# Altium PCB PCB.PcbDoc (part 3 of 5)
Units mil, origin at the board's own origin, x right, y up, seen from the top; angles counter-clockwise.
Board outline 6700 x 6500 mil, 2 copper layers (Top Layer, Bottom Layer); 203 components, 278 nets, 1296 pads, 461 vias.
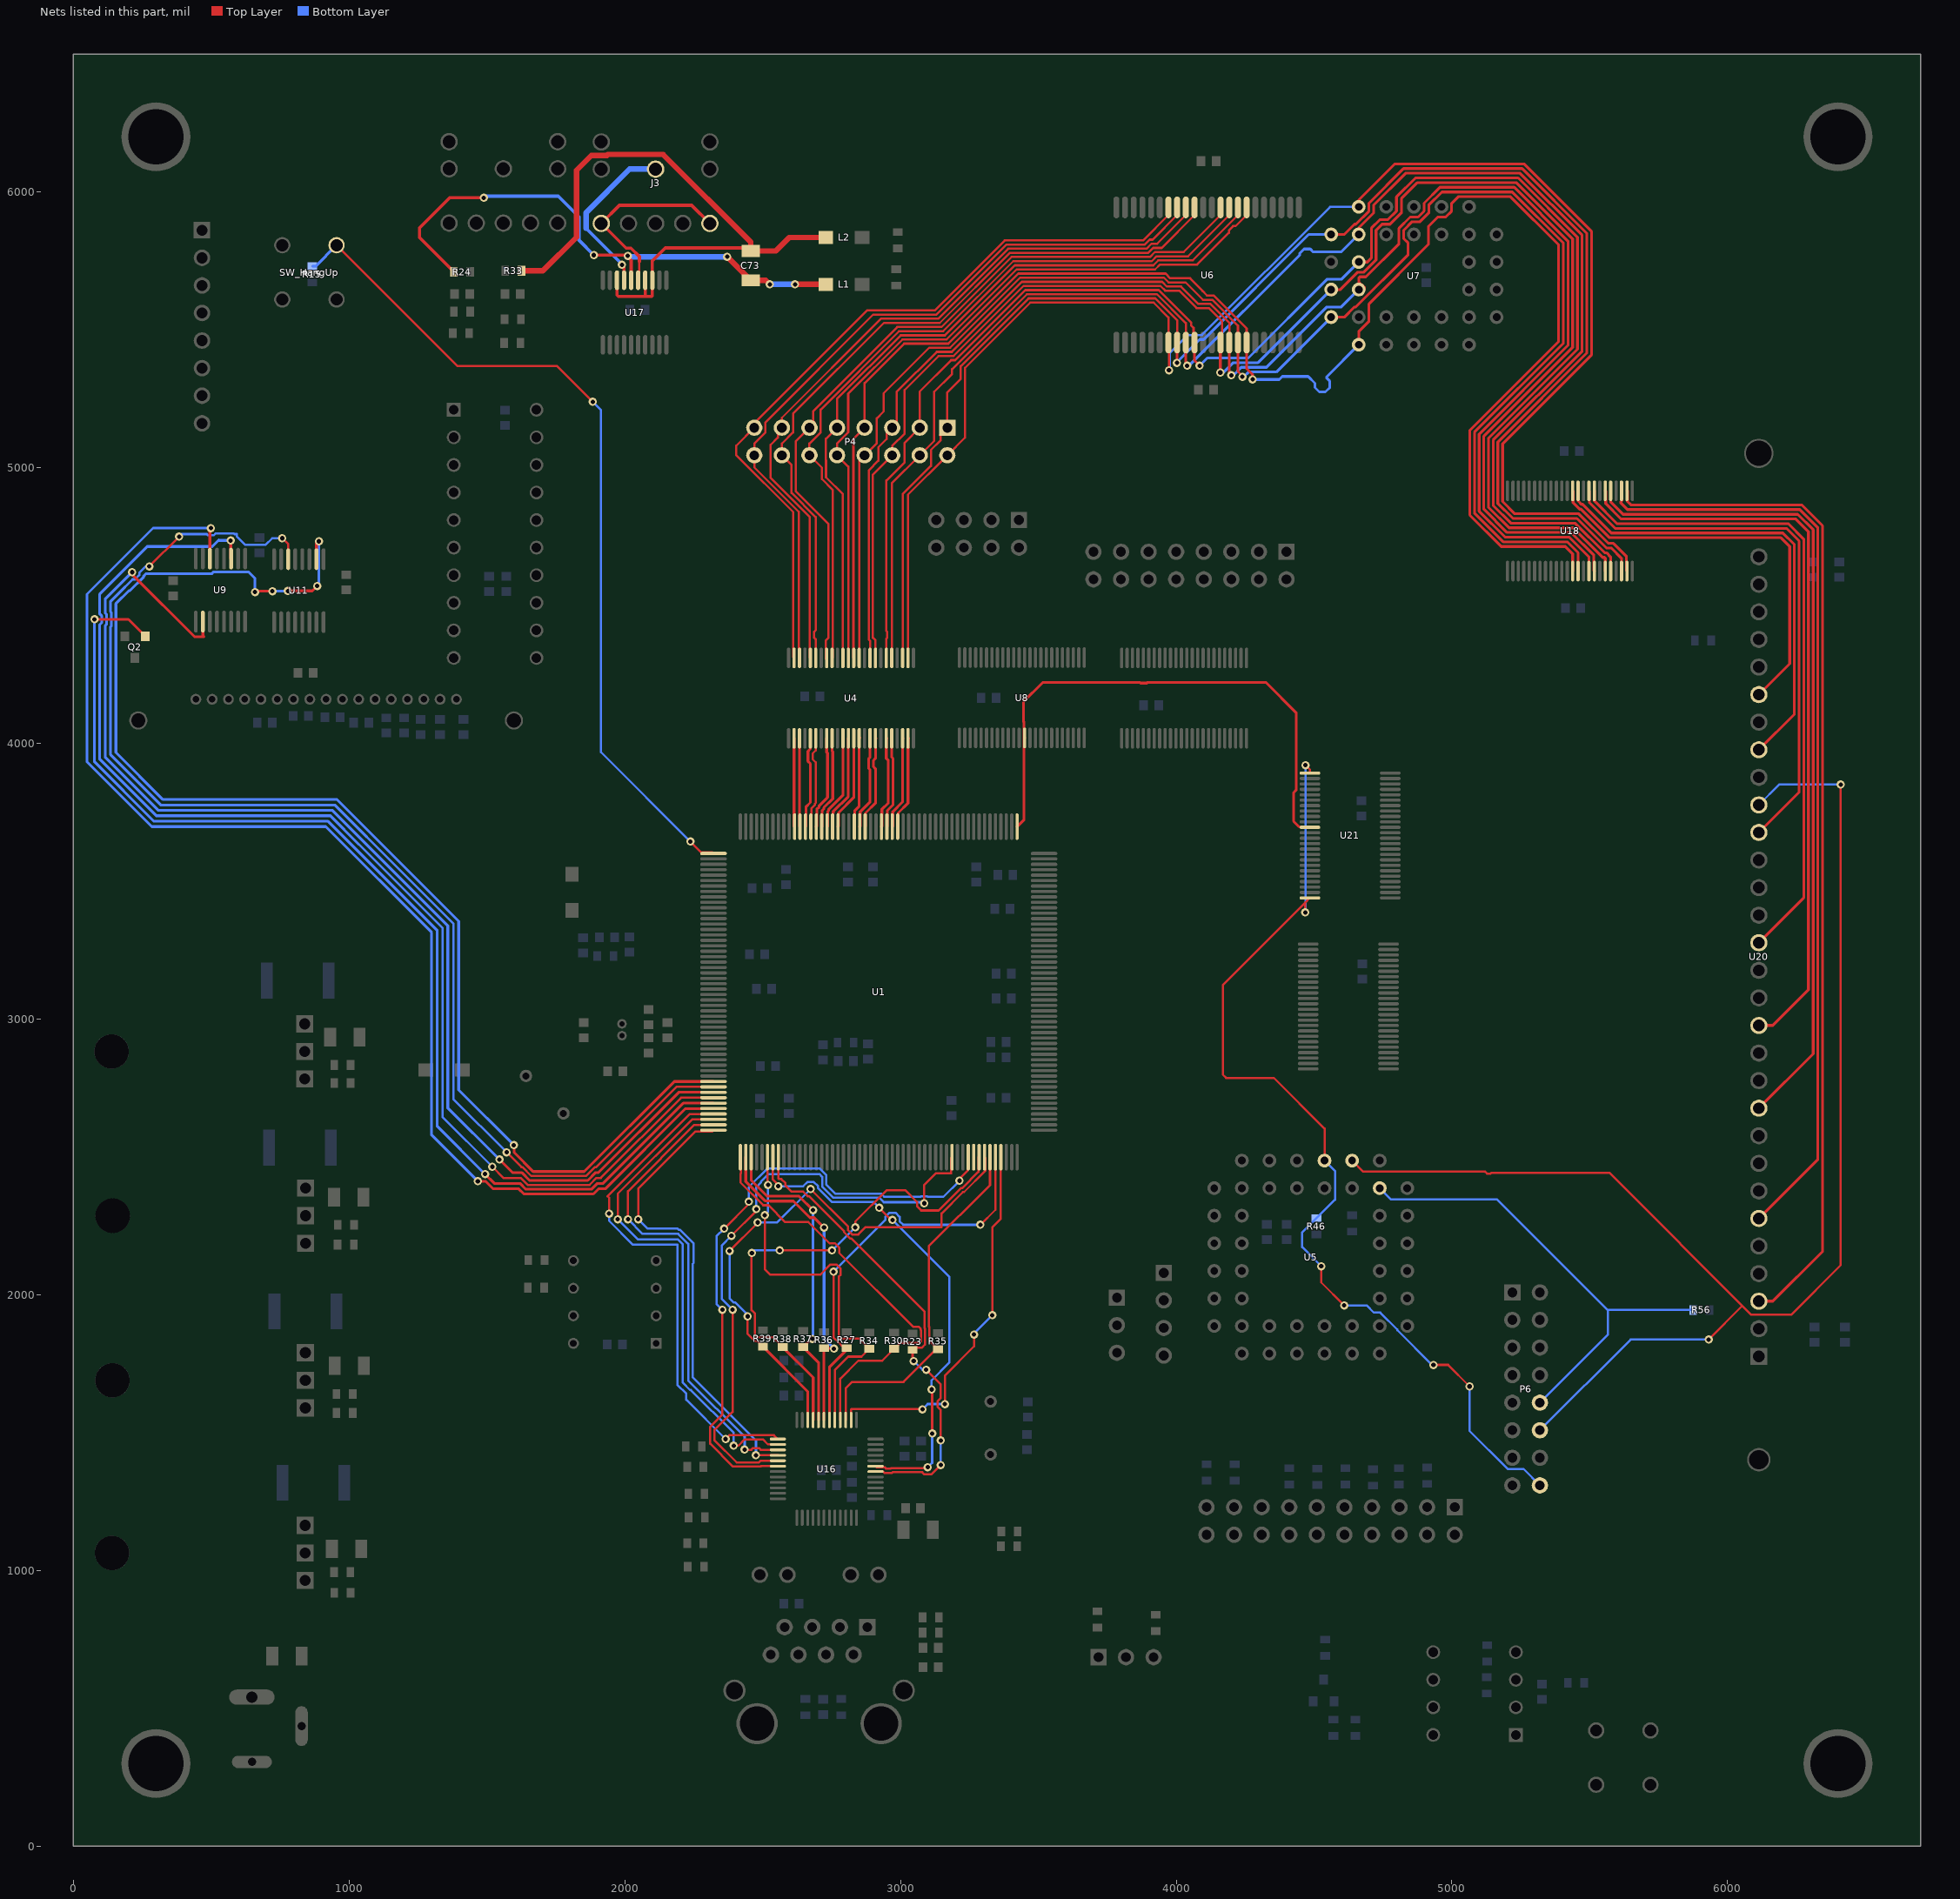
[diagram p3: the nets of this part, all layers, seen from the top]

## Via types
v1: diameter 30, hole 16, Top Layer to Bottom Layer, 461 vias

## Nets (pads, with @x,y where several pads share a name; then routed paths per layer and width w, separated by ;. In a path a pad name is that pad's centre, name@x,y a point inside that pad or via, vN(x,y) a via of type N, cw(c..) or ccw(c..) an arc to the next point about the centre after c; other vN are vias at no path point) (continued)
ADDR19: U1.157 U8.37 U21.35 | length 1997.8
  Top Layer w10: U1.157@3423.15,3698.23 3448.22,3723.3 U8.37@3448.22,4018.22 ; U8.37@3450,4020 U8.37@3448.22,4018.22 ; U21.35@4485,3695.63 4483.22,3697.41 4446.09,3697.41 4425.87,3717.63 4425.87,3821.31 4435,3830.44 4435,4111.81 4325.75,4221.06 3895.25,4221.06 3893.18,4219 3870.82,4219 3868.75,4221.06 3611.69,4221.06 3611.63,4221 3516,4221 3446,4151 3446,4078.77 3448.22,4076.55 U8.37@3448.22,4018.22
AUD_VDD: C73.2 L1.1 R24.2 U17.6 | length 2019.5
  Top Layer w8: U17.6@2023.18,5680 U17.6@2027,5683.82
  Top Layer w12: R24.2@1380.47,5710 1256,5834.47 1256,5870 1365,5979 v1(1489,5979) ; v1(1888,5771) 2004.25,5771 2009.13,5766.13 2023.18,5752.07 U17.6@2023.18,5680
  Top Layer w20: v1@2009.13,5766.13 v1(2011,5768) ; v1(2371.85,5765) C73.2@2457,5679.85 2511.15,5679.85 v1(2526,5665) ; v1(2618,5665) L1.1@2729.06,5665
  Bottom Layer w12: v1(1489,5979) 1495,5985 1759,5985 1834,5910 1834,5825 v1(1888,5771)
  Bottom Layer w20: v1(2011,5768) 2008,5765 v1(2371.85,5765) ; v1(2526,5665) v1(2618,5665)
AUD_VSS: C73.1 L2.1 R33.1 U17.3 U17.4 U17.8 | length 2353.2
  Top Layer w12: U17.8@1972,5680 1972,5626 1977,5621 2071,5621 ; U17.4@2074.36,5680 2074.36,5624.36 2071,5621 ; C73.1@2457,5786.15 2457,5797 2147,5797 2099.95,5749.95 U17.3@2099.95,5680 2099.95,5622.95 2098,5621 2071,5621
  Top Layer w20: R33.1@1625.53,5714 1703,5714 1825,5836 1825,6079 1878.78,6132.78 1935.24,6132.78 1938.46,6136 2139,6136 2457,5818 C73.1@2457,5797 ; C73.1@2457,5786.15 2548.15,5786.15 2597,5835 L2.1@2729.06,5835
BTN_HANGUP: R15.1 SW_HangUp.1 U1.1 | length 3127.1
  Top Layer w8: SW_HangUp.1@955,5806.85 1392.85,5369 1754,5369 v1(1884,5239) ; v1(2238,3644) 2277.21,3604.79 2317.77,3604.79 U1.1@2321.77,3600.79
  Bottom Layer w8: v1(1884,5239) 1914,5209 1914,3968 v1(2238,3644)
  Bottom Layer w10: R15.1@867,5730.53 878.68,5730.53 SW_HangUp.1@955,5806.85
CAS: P6.10 R56.2 U5.19 | length 1758
  Bottom Layer w8: U5.19@4738,2387 4779,2346 5164,2346 5565,1945 ; P6.10@5319,1609 5565,1855 5565,1945 ; R56.2@5875,1945 5565,1945
COL_ADDR_EN: P6.16 R46.1 U5.22 U21.25 U21.48 | length 3672.1
  Top Layer w8: v1(4468,3387) 4468,3422.73 ; v1(4469,3921) 4485,3905 U21.25@4485,3892.48 ; U21.48@4485,3439.73 4468,3422.73 ; v1(4526,2104) 4526,2045 v1(4609,1962) ; U5.22@4538,2487 4538,2603 4354,2787 4181,2787 4169,2799 4169,3123.73 4468,3422.73 ; v1(4933,1746) 4986,1746 v1(5064,1668)
  Bottom Layer w8: v1(4468,3387) 4469,3388 v1(4469,3921) ; v1(4526,2104) 4457,2173 4457,2226.53 R46.1@4509,2278.53 4576,2345.53 4576,2449 U5.22@4538,2487 ; v1(4609,1962) 4690.88,1962 4716.88,1936 4739.91,1936 4802,1873.91 4802,1872.09 4928.09,1746 v1(4933,1746) ; v1(5064,1668) 5064,1506.69 5202.21,1368.47 5259.53,1368.47 P6.16@5319,1309
D_3V3B0: P4.2 U4.2 U6.7 U7.13 U18.47 | length 5884.2
  Top Layer w8: U4.2@3027.48,4310 3027.48,4902.48 P4.2@3170,5045 3234,5109 3234,5361.8 3471.2,5599 3918,5599 3972.02,5544.98 U6.7@3972.02,5454 3974,5452.02 v1(3974,5353.67)
  Top Layer w10: U7.13@4662,5946 4662,5970.45 4793.55,6102 5261.29,6102 5506,5857.29 5506,5408.46 5183.67,5086.13 5183.67,4877.43 5228.16,4832.94 5460.35,4832.94 5567.89,4725.4 5585.52,4725.4 5632.87,4678.05 5632.87,4626.78 U18.47@5634.65,4625
  Bottom Layer w8: v1(3974,5353.67) 3976.67,5351 3976.67,5414.67 4043,5481 4093,5481 4558,5946 U7.13@4662,5946
D_3V3B1: P4.1 U4.3 U6.8 U7.14 U18.46 | length 5807.2
  Top Layer w8: U4.3@3007.8,4310 3007.8,4904.01 3110.53,5006.74 3110.53,5064.31 3145,5098.79 3145,5116.6 3144.47,5117.13 3144.47,5119.47 P4.1@3170,5145 3170,5273 3219,5322 3219,5368.02 3464.98,5614 3924.21,5614 4003.51,5534.7 U6.8@4003.51,5454
  Top Layer w10: v1(4003,5380) 4003,5447.49 4000,5450.49 U6.8@4003.51,5454 ; U7.14@4562,5846 4609.67,5846 4646.67,5883 4651.33,5883 4699,5930.67 4699,5959.37 4824.63,6085 5254.25,6085 5489,5850.25 5489,5415.5 5166.67,5093.17 5166.67,4870.38 5221.12,4815.94 5453.31,4815.94 5560.85,4708.4 5578.48,4708.4 5614.96,4671.92 U18.46@5614.96,4625
  Bottom Layer w10: v1(4003,5380) 4003,5383 4085,5465 4099.63,5465 4480.63,5846 U7.14@4562,5846
D_3V3B2: P4.4 U4.5 U6.9 U7.15 U18.44 | length 5822.9
  Top Layer w8: U4.5@2968.43,4310 2968.43,4943.43 P4.4@3070,5045 3122,5097 3122,5275 3187,5340 3187,5357.23 3458.77,5629 3930.43,5629 4035.01,5524.42 U6.9@4035.01,5454
  Top Layer w10: U6.9@4035.01,5454 4035.01,5374.99 v1(4040,5370) ; U7.15@4662,5846 4662,5869.63 4716,5923.63 4716,5952.33 4831.67,6068 5247.21,6068 5472,5843.21 5472,5422.54 5149.67,5100.21 5149.67,4863.34 5214.08,4798.94 5446.27,4798.94 5553.81,4691.4 5560.46,4691.4 5575.59,4676.28 U18.44@5575.59,4625
  Bottom Layer w10: v1(4040,5370) 4046.82,5370 4448,5771.18 4448,5777.18 4463.82,5793 4486.18,5793 4496.18,5783 4599,5783 U7.15@4662,5846
D_3V3B3: P4.3 U4.6 U6.10 U7.17 U18.43 | length 5867.8
  Top Layer w8: U4.6@2948.74,4310 2948.74,4379.97 2952,4383.23 2952,4404.77 2948.74,4408.03 2948.74,4953.74 3015,5020 3015,5090 P4.3@3070,5145 3070,5276 3184,5390 3198.56,5390 3452.56,5644 3936.64,5644 4054,5526.64 4054,5516.23 4063,5507.23 4063,5457.5 U6.10@4066.5,5454
  Top Layer w10: U6.10@4066.5,5454 4066.5,5388.5 v1(4085,5370) ; U7.17@4662,5746 4693.63,5746 4708,5760.37 4708,5868.37 4739.63,5900 4768.33,5900 4799,5930.67 4799,5982.08 4867.92,6051 5240.17,6051 5455,5836.17 5455,5429.58 5132.67,5107.25 5132.67,4856.3 5207.03,4781.94 5439.23,4781.94 5546.76,4674.4 5553.42,4674.4 5555.91,4671.92 U18.43@5555.91,4625
  Bottom Layer w10: v1(4085,5370) 4113,5398 4261.67,5398 4546.67,5683 4599,5683 U7.17@4662,5746
D_3V3B4: P4.6 U4.8 U6.13 U7.18 U18.41 | length 5954.8
  Top Layer w8: U4.8@2909.37,4310 2909.37,4373.86 2900,4383.23 2900,4975 P4.6@2970,5045 2970,5079 3015,5124 3015,5282 3138,5405 3192.35,5405 3446.35,5659 3942.85,5659 3959.85,5642 4010.77,5642 4073.77,5579 4117.77,5579 4167,5529.77 4167,5460.01 U6.13@4160.99,5454
  Top Layer w10: v1@4160.43,5344.57 v1(4160,5345) 4160,5453.01 U6.13@4160.99,5454 ; U7.18@4562,5646 4595.53,5646 4658.53,5709 4680.67,5709 4725,5753.33 4725,5861.33 4746.67,5883 4775.37,5883 4816.57,5924.2 4816.57,5975.61 4874.96,6034 5233.12,6034 5438,5829.12 5438,5436.63 5115.67,5114.3 5115.67,4849.26 5199.99,4764.94 5432.19,4764.94 5514.76,4682.37 5514.76,4626.78 U18.41@5516.54,4625
  Bottom Layer w10: v1(4160,5345) 4170.96,5345 4206.96,5381 4297,5381 U7.18@4562,5646
D_3V3B5: P4.5 U4.9 U6.14 U7.19 U18.40 | length 5953.6
  Top Layer w8: U4.9@2889.69,4310 2889.69,4372.33 2885,4377.02 2885,4990 2920,5025 2920,5073.79 2950,5103.79 2950,5125 P4.5@2970,5145 2986,5161 2986,5274.21 3131.79,5420 3186.13,5420 3440.13,5674 3949.07,5674 3966.07,5657 4017.4,5657 4080.4,5594 4123.98,5594 4192.49,5525.49 U6.14@4192.49,5454
  Top Layer w10: U6.14@4192.49,5454 4192.49,5342.51 v1(4200,5335) ; U7.19@4662,5646 4682,5646 4682,5654.28 4662.16,5674.12 4662.16,5688.59 4665.57,5692 4687.72,5692 4808,5812.28 4808,5868.37 4848.63,5909 4877.33,5909 4899,5930.67 4899,5959.37 4956.63,6017 5226.08,6017 5421,5822.08 5421,5443.67 5098.67,5121.34 5098.67,4842.22 5192.95,4747.94 5425.15,4747.94 5496.85,4676.23 U18.40@5496.85,4625
  Bottom Layer w10: v1(4200,5335) 4206.82,5335 4235.82,5364 4327.67,5364 4546.67,5583 4599,5583 U7.19@4662,5646
D_3V3B6: P4.8 U4.11 U6.15 U7.20 U18.38 | length 5943.9
  Top Layer w8: U4.11@2850.32,4310 2850.32,5025.32 P4.8@2870,5045 2914,5089 2914,5179 2939,5204 2939,5270 3104,5435 3179.92,5435 3433.92,5689 3955.28,5689 3972.28,5672 4033.9,5672 4096.9,5609 4130.2,5609 4223.98,5515.21 U6.15@4223.98,5454
  Top Layer w10: U6.15@4223.98,5454 4223.98,5349.2 4240,5333.18 v1(4240,5330) ; U7.20@4562,5546 4609.67,5546 4646.67,5583 4651.33,5583 4841.02,5772.69 4841.02,5814.65 4825,5830.67 4825,5861.33 4855.67,5892 4884.37,5892 4916,5923.63 4916,5952.33 4963.67,6000 5219.04,6000 5404,5815.04 5404,5450.71 5081.67,5128.38 5081.67,4835.18 5185.91,4730.94 5418.11,4730.94 5457.48,4691.56 U18.38@5457.48,4625
  Bottom Layer w10: v1(4240,5330) 4245.96,5330 4262.96,5347 4363,5347 U7.20@4562,5546
D_3V3B7: P4.7 U4.12 U6.16 U7.21 U18.37 | length 6118.9
  Top Layer w8: U4.12@2830.63,4310 2829.47,4311.16 2829.47,5104.47 P4.7@2870,5145 2870,5306.64 3013.36,5450 3173.71,5450 3427.71,5704 3961.49,5704 3978.49,5687 4050.39,5687 4096,5641.39 4096,5640.23 4111.23,5625 4135.41,5625 4255.48,5504.93 U6.16@4255.48,5454
  Top Layer w10: U6.16@4255.48,5454 4255.48,5359.52 4277,5338 v1(4277,5320) ; U7.21@4662,5446 4662,5493.67 4699,5530.67 4699,5594 4915,5810 4915,5875 4949,5909 4977.33,5909 4999,5930.67 4999,5959 5023,5983 5212,5983 5387,5808 5387,5457.75 5064.67,5135.42 5064.67,4828.13 5178.87,4713.94 5411.06,4713.94 5437.8,4687.21 U18.37@5437.8,4625
  Bottom Layer w10: v1(4277,5320) 4373.82,5320 4384.82,5331 4478.37,5331 4503,5306.37 4503,5290.82 4518.82,5275 4541.18,5275 4557,5290.82 4557,5313.18 4546,5324.18 4546,5330 U7.21@4662,5446
D_3V3B8: P4.10 U4.13 U6.29 | length 2738.6
  Top Layer w8: U4.13@2810.95,4310 2810.95,5004.06 P4.10@2770,5045 2770,5087.69 2810.53,5128.21 2810.53,5268.38 3007.15,5465 3167.49,5465 3421.49,5719 3923.35,5719 3941.35,5737 4076.32,5737 4191,5851.68 4191,5860.77 4206.23,5876 4215.32,5876 4255.48,5916.16 U6.29@4255.48,5944.08
D_3V3B9: P4.9 U4.14 U6.30 | length 2739.7
  Top Layer w8: U4.14@2791.26,4310 2791.26,4903.74 2730,4965 2730,5027.16 2729.47,5027.69 2729.47,5104.47 P4.9@2770,5145 2770,5249.07 3000.93,5480 3161.28,5480 3415.28,5734 3917.13,5734 3935.13,5752 4059.82,5752 4223.98,5916.16 U6.30@4223.98,5944.08
D_3V3B10: P4.12 U4.16 U6.31 | length 2755.3
  Top Layer w8: U4.16@2751.89,4310 2754,4312.11 2754,4919.79 2715,4958.79 2715,5000 P4.12@2670,5045 2670,5087.69 2710.53,5128.21 2710.53,5210.81 2994.72,5495 3155.07,5495 3409.07,5749 3910.92,5749 3928.92,5767 4043.32,5767 4192.49,5916.16 U6.31@4192.49,5944.08
D_3V3B11: P4.11 U4.17 U6.32 | length 2784.9
  Top Layer w8: U4.17@2732.21,4310 2729.43,4307.22 2729.43,4373.66 2739,4383.23 2739,4795.85 2620,4914.85 2620,5095 P4.11@2670,5145 2688.05,5163.05 2683.66,5167.44 2683.66,5205.15 2988.51,5510 3148.85,5510 3402.85,5764 3904.71,5764 3922.71,5782 4026.83,5782 4160.99,5916.16 U6.32@4160.99,5944.08
D_3V3B12: P4.14 U4.19 U6.35 | length 2740.4
  Top Layer w8: U4.19@2692.84,4310 2692.84,4377.4 2687,4383.23 2687,4404.77 2692.84,4410.6 2692.84,4820.8 2605,4908.64 2605,5010 P4.14@2570,5045 2570,5087.69 2610.53,5128.21 2610.53,5195.53 2940,5525 3142.64,5525 3396.64,5779 3898.49,5779 3916.49,5797 3947.34,5797 4066.5,5916.16 U6.35@4066.5,5944.08
D_3V3B13: P4.13 U4.20 U6.36 | length 2749.9
  Top Layer w8: P4.13@2586.16,5164.94 P4.13@2588.05,5163.05 ; U4.20@2673.15,4310 2670.37,4312.78 2670.37,4822.06 2529.47,4962.95 2529.47,5083.26 2555,5108.79 2555,5123.9 2551.95,5126.95 P4.13@2570,5145 2570,5181 2929,5540 3136.43,5540 3390.43,5794 3892.28,5794 3910.28,5812 3930.84,5812 4035.01,5916.16 U6.36@4035.01,5944.08
D_3V3B14: P4.16 U4.22 U6.37 | length 2778.3
  Top Layer w8: U4.22@2633.78,4310 2636.56,4312.78 2636.56,4343.4 2632.99,4343.4 2631.98,4342.39 2631,4342.39 2631,4840.21 2470,5001.21 P4.16@2470,5045 2470,5087.69 2510.53,5128.21 2510.53,5164.31 2901.21,5555 3130.21,5555 3384.21,5809 3886.07,5809 3904.07,5827 3914.35,5827 4003.51,5916.16 U6.37@4003.51,5944.08
D_3V3B15: P4.15 U4.23 U6.38 | length 2807.3
  Top Layer w8: U4.23@2614.1,4310 2611.32,4312.78 2611.32,4838.68 2405,5045 2405,5080 P4.15@2470,5145 2470,5161 2879,5570 3124,5570 3378,5824 3879.85,5824 3972.02,5916.16 U6.38@3972.02,5944.08
D_5V0: U18.2 U20.3 | length 3723.3
  Top Layer w10: U18.2@5636.42,4916.34 U18.2@5634.65,4916.34 5636.42,4914.56 5636.42,4877.43 5648.85,4865 6268.29,4865 6344,4789.29 6344,2157.09 6163.91,1977 U20.3@6113,1977
D_5V1: U18.3 U20.6 | length 3392.1
  Top Layer w10: U18.3@5614.96,4916.34 5616.74,4914.56 5616.74,4880.78 5613,4877.04 5613,4871.38 5636.38,4848 6261.25,4848 6327,4782.25 6327,2491 U20.6@6113,2277
D_5V2: U18.5 U20.10 | length 2996.1
  Top Layer w10: U18.5@5575.59,4916.34 5575.59,4876.33 5620.92,4831 6254.21,4831 6310,4775.21 6310,2874 U20.10@6113,2677
D_5V3: U18.6 U20.13 | length 2720
  Top Layer w10: U18.6@5555.91,4916.34 5557.68,4914.56 5557.68,4870.19 5613.88,4814 6247.17,4814 6293,4768.17 6293,3106.09 6163.91,2977 U20.13@6113,2977
D_5V4: U18.8 U20.16 | length 2385.4
  Top Layer w10: U18.8@5516.54,4916.34 5516.54,4879.2 5598.74,4797 6220.12,4797 6276,4741.12 6276,3440 U20.16@6113,3277
D_5V5: U18.9 U20.20 | length 1979.5
  Top Layer w10: U18.9@5496.85,4916.34 5498.63,4914.56 5498.63,4873.07 5591.7,4780 6213.08,4780 6259,4734.08 6259,3823 U20.20@6113,3677
D_5V6: U18.11 U20.23 | length 1684.6
  Top Layer w10: U18.11@5457.48,4916.34 5457.48,4879.2 5469.75,4866.94 5474.44,4866.94 5578.37,4763 6200.04,4763 6242,4721.04 6242,4106 U20.23@6113,3977
D_5V7: U18.12 U20.25 | length 1478.7
  Top Layer w10: U18.12@5437.8,4916.34 5439.57,4914.56 5439.57,4873.07 5462.71,4849.94 5467.4,4849.94 5571.33,4746 6193,4746 6225,4714 6225,4289 U20.25@6113,4177
DATA0: U1.179 U4.47 | length 337.7
  Top Layer w10: U1.179@2990.08,3698.23 2991.86,3700.01 2991.86,3747.97 3027.48,3783.59 U4.47@3027.48,4018.66 U4.47@3029.26,4018.66
DATA1: U1.180 U4.46 | length 337.7
  Top Layer w10: U1.180@2970.39,3698.23 2972.17,3700.01 2972.17,3752.32 3007.8,3787.95 U4.46@3007.8,4018.66 U4.46@3009.57,4018.66
DATA2: U1.181 U4.44 | length 333.4
  Top Layer w10: U1.181@2950.71,3698.23 2952.49,3700.01 2952.49,3756.68 2973.06,3777.25 2973.06,3945.28 2968.43,3949.91 U4.44@2968.43,4018.66 U4.44@2970.2,4018.66
DATA3: U1.182 U4.43 | length 335.6
  Top Layer w10: U1.182@2931.02,3698.23 2932.8,3700.01 2932.8,3761.04 2956.06,3784.29 2956.06,3938.24 2948.74,3945.55 U4.43@2948.74,4018.66 U4.43@2950.52,4018.66
DATA4: U1.185 U4.41 | length 343.8
  Top Layer w10: U1.185@2871.97,3698.23 2873.75,3700.01 2873.75,3747.97 2909.37,3783.59 2909.37,3908.56 2902.06,3915.87 2902.06,3938.24 2909.37,3945.55 U4.41@2909.37,4018.66 U4.41@2911.15,4018.66
DATA5: U1.186 U4.40 | length 342.3
  Top Layer w10: U1.186@2852.28,3698.23 2854.06,3700.01 2854.06,3752.32 2889.69,3787.95 2889.69,3904.2 2885.06,3908.83 2885.06,3945.28 2889.69,3949.91 U4.40@2889.69,4018.66 U4.40@2891.46,4020.44
DATA6: U1.187 U4.38 | length 330.3
  Top Layer w10: U1.187@2832.6,3698.23 2834.38,3700.01 2834.38,3756.68 2850.32,3772.62 U4.38@2850.32,4018.66 U4.38@2852.09,4020.44
DATA7: U1.190 U4.37 | length 344.1
  Top Layer w10: U1.190@2773.54,3698.23 2775.32,3700.01 2775.32,3747.97 2830.63,3803.27 U4.37@2830.63,4018.66
DATA8: U1.191 U4.36 | length 344.1
  Top Layer w10: U1.191@2753.86,3698.23 2755.64,3700.01 2755.64,3747.97 2756.25,3748.58 2756.25,3752.94 2810.95,3807.63 U4.36@2810.95,4018.66
DATA9: U1.192 U4.35 | length 344.1
  Top Layer w10: U1.192@2734.17,3698.23 2735.95,3700.01 2735.95,3752.32 2739.25,3755.62 2739.25,3759.98 2791.26,3811.99 U4.35@2791.26,4018.66
DATA10: U1.193 U4.33 | length 338.2
  Top Layer w10: U1.193@2714.49,3698.23 2716.27,3700.01 2716.27,3756.68 2722.25,3762.66 2722.25,3767.02 2754.63,3799.4 2754.63,3969.6 2752.56,3971.67 2752.56,4017.99 U4.33@2751.89,4018.66
DATA11: U1.194 U4.32 | length 338.7
  Top Layer w10: U1.194@2694.8,3698.23 2696.58,3700.01 2696.58,3741.46 2696.58,3761.04 2705.25,3769.7 2705.25,3774.06 2735.56,3804.37 2735.56,3964.62 2732.21,3967.98 U4.32@2732.21,4018.66
DATA12: U1.195 U4.30 | length 337
  Top Layer w8: U1.195@2675.12,3698.23 2677.9,3701.01 2677.9,3764.98 2689.25,3776.33 2689.25,3780.69 2693,3784.44 2693,3931.23 2682,3942.23 2682,3963.77 2693,3974.77 2693,4018.5 U4.30@2692.84,4018.66
DATA13: U1.196 U4.29 | length 334.9
  Top Layer w10: U1.196@2655.43,3698.23 2657.21,3700.01 2657.21,3769.75 2673.15,3785.69 2673.15,3926.62 2664.56,3935.22 2664.56,3971.67 2673.15,3980.26 U4.29@2673.15,4018.66
DATA14: U1.197 U4.27 | length 321.2
  Top Layer w10: U4.27@2633.78,4018.66 2633.97,4018.47 2633.97,3700.01 U1.197@2635.75,3698.23
DATA15: U1.198 U4.26 | length 321.2
  Top Layer w10: U4.26@2614.1,4018.66 2614.28,4018.47 2614.28,3700.01 U1.198@2616.06,3698.23
DISP_A0: U1.46 U9.3 | length 4626.9
  Top Layer w8: v1(1519.51,2464.51) 1560.08,2423.94 1623.17,2423.94 1648.12,2399 1872.69,2399 1897.63,2423.94 1913.27,2423.94 2204.28,2714.96 U1.46@2321.77,2714.96
  Top Layer w10: v1(571,4736) 571,4671.56 U9.3@572.39,4670.17
  Bottom Layer w8: 1035.84,3633.84 1338.94,3330.73 1338.94,2645.08 v1(1519.51,2464.51)
  Bottom Layer w10: v1(571,4736) 529.41,4736 527.8,4737.61 504.18,4714 268.14,4714 95.94,4541.81 95.94,4469.24 104,4461.18 104,4438.82 95.94,4430.76 95.94,3942.54 301.11,3737.37 932.31,3737.37 1035.84,3633.84
DISP_BCKLIGHT: Q2.G U1.47 | length 4159.2
  Top Layer w10: v1(77,4450) 200.14,4450 Q2.G@261.4,4388.74 ; v1(1493.35,2438.35) 1527.44,2404.26 1620.23,2404.26 1641.49,2383 1879.31,2383 1900.57,2404.26 1921.42,2404.26 2212.44,2695.28 U1.47@2321.77,2695.28
  Bottom Layer w10: v1(77,4450) 76.26,4449.26 76.26,3934.38 292.96,3717.69 924.15,3717.69 1319.26,3322.58 1319.26,2612.44 v1(1493.35,2438.35)
DISP_CS: U1.45 U9.10 | length 4495.8
  Top Layer w10: v1(213.32,4621) 213.32,4613.29 439.61,4387 474,4387 470.02,4390.98 U9.10@470.02,4441.83 ; v1(1545.67,2490.67) 1592.72,2443.63 1626.12,2443.63 1654.75,2415 1866.06,2415 1894.69,2443.63 1905.11,2443.63 2196.13,2734.65 U1.45@2321.77,2734.65
  Bottom Layer w10: v1(213.32,4621) 115.63,4523.31 115.63,4473.6 121,4468.23 121,4431.77 115.63,4426.4 115.63,3950.69 309.27,3757.06 940.46,3757.06 1358.63,3338.89 1358.63,2677.72 v1(1545.67,2490.67)
DISP_MOSI: U1.43 U11.10 | length 4938.6
  Top Layer w10: v1(659,4549) 662,4552 v1(722,4552) ; v1(778,4553) 867,4553 v1(885,4571) ; U11.10@881.98,4668.17 881.98,4729.98 891,4739 v1(891,4733) ; v1(1598,2543) 1598.84,2542.16 1598.84,2516.16 1668,2447 1852.8,2447 2179.82,2774.02 U1.43@2321.77,2774.02
  Bottom Layer w10: v1(659,4549) 659,4598 635,4622 508.82,4622 501.82,4615 263,4615 255.32,4607.32 255.32,4603.6 205.72,4554 202,4554 155,4507 155,3967 325.57,3796.43 956.77,3796.43 1398,3355.2 1398,2743 v1(1598,2543) ; v1(722,4552) 777,4552 v1(778,4553) ; v1(885,4571) 891,4577 v1(891,4733)
DISP_RST: U1.48 U9.6 | length 4748.3
  Top Layer w10: U9.6@495.61,4670.17 495.61,4777.61 v1(499,4781) ; v1(1467.19,2412.19) 1468.02,2411.35 1496.31,2411.35 1523.08,2384.57 1615.87,2384.57 1634.45,2366 1886.36,2366 1904.93,2384.57 1929.57,2384.57 2220.59,2675.59 U1.48@2321.77,2675.59
  Bottom Layer w10: v1(499,4781) 289.8,4781 50,4541.2 50,3932.8 284.8,3698 916,3698 1299.57,3314.43 1299.57,2579.8 v1(1467.19,2412.19)
DISP_SCK: U1.44 U11.14 | length 4735.6
  Top Layer w8: v1(276,4642) v1(384,4750) ; v1(758,4744) 779.61,4722.39 U11.14@779.61,4668.17 ; v1(1571.84,2516.84) 1625.36,2463.31 1629.06,2463.31 1661.37,2431 1859.43,2431 1891.75,2463.31 1896.96,2463.31 2187.97,2754.33 U1.44@2321.77,2754.33
  Bottom Layer w8: 188.08,4567.92 215.16,4595 224.09,4595 239.32,4610.23 239.32,4619.16 262.16,4642 v1(276,4642) ; v1(384,4750) 393,4759 484.23,4759 488.23,4755 509.77,4755 516.77,4762 581.77,4762 584.77,4759 594,4759 594,4750.23 624.42,4719.81 697.27,4719.81 721.46,4744 v1(758,4744) ; 1063.68,3661.68 1378.31,3347.04 1378.31,2710.36 v1(1571.84,2516.84)
  Bottom Layer w10: 188.08,4567.92 135.31,4515.15 135.31,4477.95 138,4475.27 138,4424.73 135.31,4422.05 135.31,3958.85 317.42,3776.74 948.62,3776.74 1063.68,3661.68
DRAM_WE: P6.12 U5.20 U20.21 | length 5072.1
  Top Layer w8: U5.20@4638,2487 4678,2447 5120.21,2447 5127.21,2440 5140.23,2440 5143.23,2443 5571,2443 6086,1928 6230,1928 6410,2108 v1(6410,3851) ; v1(5931,1838) 6053,1960
  Bottom Layer w8: P6.12@5319,1509 5648,1838 v1(5931,1838) ; U20.21@6113,3777 6187,3851 v1(6410,3851)
EAROUT+: J3.A J3.D U17.5 | length 723.4
  Top Layer w8: U17.5@2048.77,5680 2053,5684.23 2053,5748.15
  Top Layer w12: 2053,5748.15 2053,5765.6 2022.6,5796 2005.15,5796 J3.D@1915.15,5886 1981.15,5952 2242.85,5952 J3.A@2308.85,5886
EAROUT-: J3.E U17.7 | length 619.4
  Top Layer w12: v1(1990,5736) 1997.59,5728.41 U17.7@1997.59,5680
  Bottom Layer w12: 1860,5868 1990,5738 v1(1990,5736)
  Bottom Layer w20: 1860,5868 1860,5925 2017.85,6082.85 J3.E@2112,6082.85
ECOL: R27.1 U1.100 U16.42 | length 1512.8
  Top Layer w8: v1(2757,2084) 2757,1845.26 2776.51,1825.75 2777.02,1825.75 2786,1816.77 2786,1816.26 2795.79,1806.47 R27.1@2805,1806.47 ; v1(3290,2254) 3344.41,2308.41 U1.100@3344.41,2499.41
  Top Layer w10: U16.42@2742.31,1546 2742.31,1737.31 2805,1800 R27.1@2805,1806.47
  Bottom Layer w8: v1(2757,2084) 2945,2272 2945,2282.77 2960.23,2298 2981.77,2298 2997,2282.77 2997,2267.21 3010.21,2254 v1(3290,2254)
ECRS: R30.1 U1.53 U16.40 | length 1529.9
  Top Layer w8: U1.53@2419.21,2499.41 2421.99,2502.19 2421.99,2441.62 2420,2439.63 2420,2407.33 2502.33,2325 2521.37,2325 2582.37,2264 2666.23,2264 2743.23,2187 2762.77,2187 2778,2171.77 2778,2152.23 3045.92,1884.31 3066.27,1884.31 3072.72,1877.86 3072.72,1873.28 3074,1872 3074,1830.48 3067.52,1824 3066.27,1825.25 2997.78,1825.25 R30.1@2977,1804.47 2933.53,1761 2847,1761 2781.68,1695.68 U16.40@2781.68,1546
EMDC: U1.59 U16.31 | length 1806.8
  Top Layer w8: U1.59@2537.32,2499.41 2537.32,2418.45 2557,2398.77 v1(2557,2394) ; U16.31@2909.64,1378.68 2913.4,1374.91 2942.36,1374.91 2947.28,1370 2963.8,1370 2965.8,1372 3096,1372 v1(3099,1375) ; v1(2923,2316) 2967,2272 v1(2971,2272) ; v1(3113,1657) 3115,1655 v1(3115,1497)
  Bottom Layer w8: v1(2557,2394) 2647.23,2394 2663.23,2410 2684.77,2410 2701,2393.77 2701,2386.8 2750.8,2337 2902,2337 v1(2923,2316) ; v1(2971,2272) 3177,2066 3177,1754 3113,1690 v1(3113,1657) ; v1(3099,1375) 3115,1391 v1(3115,1497)
EMDIO: R23.2 U1.60 U16.30 | length 1722.6
  Top Layer w8: U1.60@2557.01,2499.41 2557.01,2421.99 2559,2420 2567.77,2420 2583,2404.77 2583,2396 2605,2374 2647.23,2374 2663.23,2358 2668.77,2358 2795,2231.77 2795,2228.02 2819.02,2204 2822.77,2204 3087.72,1939.05 3087.72,1879.5 3089,1878.21 3089,1819.79 3078.21,1809 3061.31,1809 3060.06,1810.25 3053.78,1810.25 R23.2@3044,1800.47 3044,1764 v1(3048,1760) ; U16.30@2909.64,1358.99 2937.07,1358.99 2941.76,1354.31 2969.32,1354.31 2972.02,1357 3078.98,1357 3086.98,1349 3112,1349 v1(3146,1383) ; v1(3093,1728) 3146,1675 3146,1625.77 3135,1614.77 3135,1593.23 3146,1582.23 v1(3146,1472)
  Bottom Layer w8: v1(3048,1760) 3080,1728 v1(3093,1728) ; v1(3146,1383) v1(3146,1472)
ERX0: R36.2 U1.54 U16.43 | length 1194.4
  Top Layer w10: U1.54@2438.9,2499.41 2438.9,2411.06 2508.96,2341 2528,2341 2529,2340 2611.82,2340 2671.82,2280 2687,2280 v1(2723,2244) ; U16.43@2722.63,1546 2722.63,1806.1 R36.2@2723,1806.47 2759.53,1806.47 2759,1805.94 v1(2759,1805)
  Bottom Layer w10: v1(2723,2244) 2723,1841 v1(2759,1805)
ERX1: R37.2 U1.55 U16.44 | length 1155
  Top Layer w10: U1.55@2458.58,2499.41 2458.58,2415.42 2516,2358 2632,2358 v1(2683,2307) ; v1(2681,1840) 2676.53,1840 R37.2@2647,1810.47 2702.94,1754.53 U16.44@2702.94,1546
  Bottom Layer w10: v1(2681,1840) 2683,1842 v1(2683,2307)
ERX2: R38.2 U1.97 U16.45 | length 1815.1
  Top Layer w8: v1(2461,2152) 2460,2151 2460,1944.77 2472.28,1932.49 2472.28,1853.19 2478.73,1846.75 2536.72,1846.75 R38.2@2573,1810.47 ; v1(2562,2161) v1(2752,2161) ; v1(2836,2245) 2836,2265.77 2950.23,2380 3016.79,2380 3060,2336.79 3060,2321.23 3075.23,2306 3138.49,2306 3220.49,2388 3224.77,2388 3282.58,2445.81 3282.58,2499.41 U1.97@3285.35,2499.41
  Top Layer w10: R38.2@2573,1810.47 2683.26,1700.21 U16.45@2683.26,1546
  Bottom Layer w8: v1(2461,2152) 2470,2161 v1(2562,2161) ; v1(2752,2161) v1(2836,2245)
ERX3: R39.1 U1.98 U16.46 | length 2012.9
  Top Layer w8: v1(2380,2159) 2482,2261 v1(2482,2262.67) ; v1(2446,1922) 2446,1858.26 2472.51,1831.75 2481.72,1831.75 R39.1@2501,1812.47 ; v1(2674,2384) 2810,2248 2810,2234.23 2825.23,2219 2846.77,2219 2873.77,2246 3149,2246 3149,2295.3 3226.7,2373 3230.98,2373 3307.82,2449.84 3307.82,2496.63 U1.98@3305.04,2499.41
  Top Layer w10: R39.1@2501,1812.47 2663.57,1649.9 U16.46@2663.57,1546
  Bottom Layer w8: v1(2380,2159) 2380,1988 2396,1972 2401.77,1972 2446,1927.77 v1(2446,1922) ; v1(2482,2262.67) 2482.33,2263 2553,2263 v1(2674,2384)
ERXCK: U1.101 U16.38 | length 1369.3
  Top Layer w8: U16.38@2821.05,1546 2821.05,1585.05 2822.53,1586.53 3078.58,1586.53 v1(3080.05,1585.05) ; v1(3161,1604) 3161,1707 3267,1813 v1(3267,1856) ; v1(3333,1926) 3333,2245 3364.1,2276.1 U1.101@3364.1,2499.41
  Bottom Layer w8: v1(3080.05,1585.05) 3099,1604 v1(3161,1604) ; v1(3267,1856) 3265,1858 v1(3333,1926)
ERXDV: R35.1 U1.99 U16.39 | length 1310.3
  Top Layer w8: U16.39@2801.37,1546 2801.37,1660.37 2825,1684 3011,1684 3129.47,1802.47 R35.1@3136,1802.47 3104,1834.47 3104,1884.43 3103,1885.43 3103,2176 3324.73,2397.73 U1.99@3324.73,2499.41
ERXER: R34.1 U1.58 U16.41 | length 1433.3
  Top Layer w8: v1(2508,2289) 2508,2093 2527,2074 2710.23,2074 2746.23,2110 2767.77,2110 2783,2094.77 2783,2073.23 2776.28,2066.51 2776.28,1847.19 2782.73,1840.75 2850.72,1840.75 R34.1@2887,1804.47 2858.53,1776 2811,1776 2762,1727 U16.41@2762,1546 ; U1.58@2517.64,2499.41 2517.64,2401.36 v1(2520,2399)
  Bottom Layer w8: v1(2508,2289) 2520,2301 v1(2520,2399)
ETX0: U1.51 U16.3 | length 1723.4
  Top Layer w8: v1(2012,2274) 2012,2375.84 2252.7,2616.54 U1.51@2321.77,2616.54 ; v1(2435,1439) 2436.27,1437.73 2458.96,1437.73 2465.28,1444.05 2486.82,1444.05 2493.13,1437.73 U16.3@2555.31,1437.73
  Bottom Layer w8: v1(2012,2274) 2064.69,2221.31 2194.06,2221.31 2230.37,2185 2230.37,1689.79 2435,1485.16 v1(2435,1439)
ETX1: U1.52 U16.4 | length 1653.6
  Top Layer w8: v1(2049,2274) 2049,2385 2256.85,2592.85 2317.77,2592.85 U1.52@2321.77,2596.85 ; v1(2476.05,1418.05) U16.4@2555.31,1418.05
  Bottom Layer w8: v1(2049,2274) 2082,2241 2191,2241 2195.69,2236.31 2200.27,2236.31 2250.06,2186.53 2250.06,2116.01 2245.91,2111.87 2245.91,1702.09 2476.05,1471.95 v1(2476.05,1418.05)
ETX2: U1.92 U16.5 | length 2215.3
  Top Layer w8: v1(2387,2214) 2477,2304 v1(2477,2311) ; v1(2391,1946) 2391,1575 2325,1509 2325,1473 2405.95,1392.05 2486.82,1392.05 2493.13,1398.36 U16.5@2555.31,1398.36 ; v1(3086,2332) 3086,2398.48 3127.7,2440.18 3184.03,2440.18 3184.15,2440.3 3184.15,2496.63 U1.92@3186.93,2499.41
  Bottom Layer w8: v1(2387,2214) 2352.69,2179.69 2352.69,1984.31 v1(2391,1946) ; v1(2477,2311) 2477,2390.16 2493.92,2407.08 2493.92,2409.69 2522.23,2438 2706,2438 2716,2428 2716,2393.02 2757.02,2352 2923.77,2352 2939.77,2336 3082,2336 v1(3086,2332)
ETX3: U1.95 U16.6 | length 2265.7
  Top Layer w8: v1(2354,1946) 2354,1565.84 2310,1521.84 2310,1460.16 2393.11,1377.05 2493.03,1377.05 2494.66,1378.68 U16.6@2555.31,1378.68 ; v1(2360.84,2240.16) 2450,2329.33 v1(2450,2338) ; v1(3214,2414) 3214,2420.88 3243.21,2450.09 3243.21,2496.63 U1.95@3245.98,2499.41
  Bottom Layer w8: v1(2354,1946) 2333,1967 2333,2212.33 v1(2360.84,2240.16) ; v1(2450,2338) 2450,2391 2516.69,2457.69 2707.53,2457.69 2731,2434.21 2731,2399.23 2763.23,2367 2929.98,2367 2941.3,2355.69 3072.92,2355.69 3075.23,2358 3096.77,2358 3099.08,2355.69 3155.69,2355.69 v1(3214,2414)
ETXCK: U1.49 U16.1 | length 1861.1
  Top Layer w8: v1(1943,2294.33) 1943,2352.52 1938,2357.52 2236.39,2655.91 U1.49@2321.77,2655.91 ; v1(2365.9,1477.1) 2379.8,1491 2541.41,1491 U16.1@2555.31,1477.1
  Bottom Layer w8: v1(1943,2294.33) 1943,2269 2030.06,2181.94 2191,2181.94 2191,2160.77 2192,2159.77 2192,1674.48 2191,1673.48 2223.24,1641.24 2223.24,1619.76 v1(2365.9,1477.1)
ETXEN: U1.50 U16.2 | length 1810.2
  Top Layer w8: v1(1975,2274) 1975,2366.68 2244.54,2636.22 U1.50@2321.77,2636.22 ; v1(2395,1453) 2412.23,1453 2435.23,1476 2500.77,1476 2519.35,1457.42 U16.2@2555.31,1457.42
  Bottom Layer w8: v1(1975,2274) 2047.37,2201.63 2192.53,2201.63 2210.69,2183.47 2210.69,1681.64 2237.16,1655.16 2239.84,1655.16 2395,1500 v1(2395,1453)
ETXER: U1.96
